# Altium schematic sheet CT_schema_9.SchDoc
size 277 x 170 mm
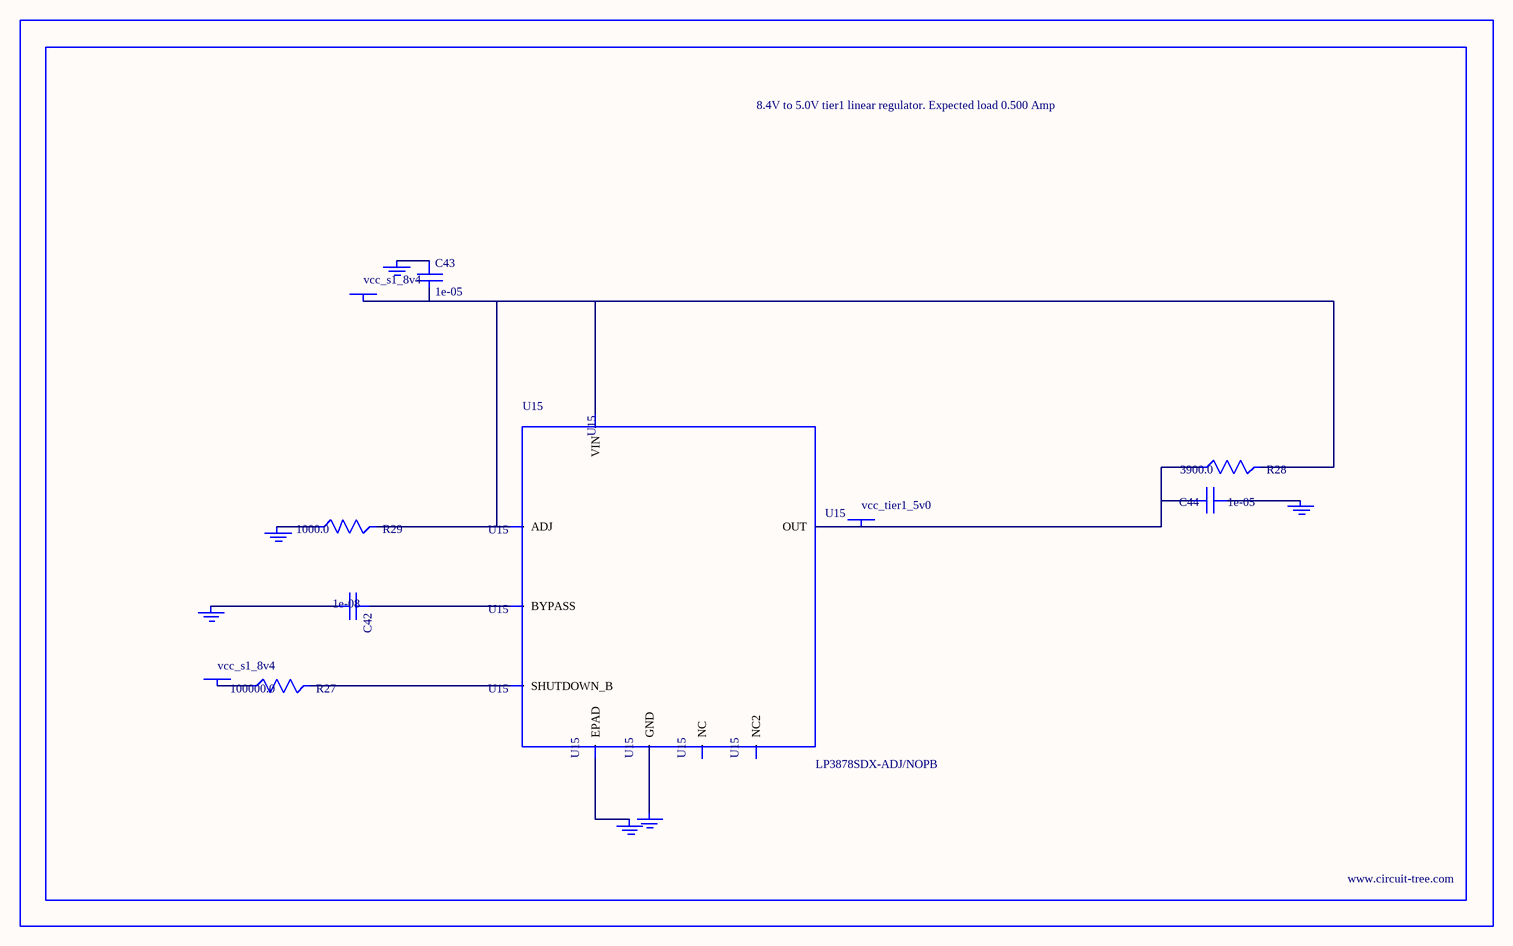
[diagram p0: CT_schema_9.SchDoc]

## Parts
BORDER8  (no value)
C42  1e-08  [C0402]
C43  1e-05  [C1206]
C44  1e-05  [C1210]
GND_INSTANCE_8_0  (no value)
GND_INSTANCE_8_1  (no value)
GND_INSTANCE_8_2  (no value)
GND_INSTANCE_8_3  (no value)
GND_INSTANCE_8_4  (no value)
GND_INSTANCE_8_5  (no value)
POWER_INSTANCE_8_0  vcc_s1_8v4
POWER_INSTANCE_8_1  vcc_s1_8v4
POWER_INSTANCE_8_2  vcc_tier1_5v0
R27  100000.0  [R0603]
R28  3900.0  [R0603]
R29  1000.0  [R0603]
U15  LP3878SDX-ADJ/NOPB  [WSON-8]

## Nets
NetC42_1: C42.1 U15.1(BYPASS)
NetC42_2: C42.2 GND_INSTANCE_8_0.0(GND)
NetC43_1: C43.1 GND_INSTANCE_8_1.0(GND)
NetC43_2: C43.2 POWER_INSTANCE_8_0.0(PWR) R28.2 R29.2 U15.4(VIN) U15.6(ADJ)
NetC44_1: C44.1 GND_INSTANCE_8_2.0(GND)
NetC44_2: C44.2 POWER_INSTANCE_8_2.0(PWR) R28.1 U15.5(OUT)
NetGND_INSTANCE_8_3_0: GND_INSTANCE_8_3.0(GND) R29.1
NetGND_INSTANCE_8_4_0: GND_INSTANCE_8_4.0(GND) U15.PAD(EPAD)
NetGND_INSTANCE_8_5_0: GND_INSTANCE_8_5.0(GND) U15.3(GND)
NetPOWER_INSTANCE_8_1_0: POWER_INSTANCE_8_1.0(PWR) R27.1
NetR27_2: R27.2 U15.8(SHUTDOWN_B)

Not connected (* = marked no-connect by the designer): U15 2(NC) 7(NC2)

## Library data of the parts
BORDER8 = BORDER_PAGE8
C42 = C0402C103K3RAC
C43 = C1206C106K3RACTU
C44 = GRM32DR61E106MA12L
GND_INSTANCE_8_0-GND_INSTANCE_8_5 = GND
POWER_INSTANCE_8_0-POWER_INSTANCE_8_2 = PWR
R27 = RC0603JR-07100KL
R28 = RC0603JR-073K9L
R29 = RC0603JR-071KL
